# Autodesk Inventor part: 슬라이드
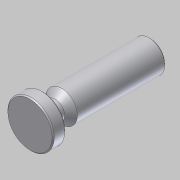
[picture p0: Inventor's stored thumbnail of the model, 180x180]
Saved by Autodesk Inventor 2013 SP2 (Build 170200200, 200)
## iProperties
Created: 2014-03
Part Number: 슬라이드
Document SubType Name: Modeling
Designer: SeoGD™[esajin.kr]
Density: 1 g/cm^3
Material: 일반
Author: SeoGD™[esajin.kr]
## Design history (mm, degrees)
sketch "스케치1"
  geometry: L1 (7.5, 114.5)-(7.5, 91.5) reference; L2 (13, 91)-(-13, 91) reference; L3 (0, 126)-(0, 69); L4 (0, 69)-(11, 69); L5 (11, 69)-(11, 75); L6 (11, 75)-(4.5, 75); L7 (4.5, 75)-(4.5, 81); L8 (4.5, 81)-(7.5, 84); L9 (7.5, 84)-(7.5, 126); L10 (7.5, 126)-(0, 126); 2 further points
  constraints: 18 end point, 4 parallel, 3 perpendicular, 1 collinear, 1 midpoint, 1 point on line, 1 vertical, 2 other
  dimensions: "d0" = 57 distance of L3.start L3.end; "d1" = 6 distance of L4.end L5.end; "d2" = 45 deg angle of L8 L7; "d3" = 9 diameter of L7 L3; "d4" = 15 distance from line of L4 L8.end; "d5" = 22 distance from line of L3.end L2; "d6" = 22 diameter of L5 L3
revolve "회전1" sketch "스케치1" stored, may be unused: angle "d7" = 90 deg
chamfer "모따기1" distance "d8" = 0.5; stored, may be unused: second distance "d9" = 2, angle "d10" = 45 deg
fillet "모깎기1" dims "d11" = 0.3
node "솔리드1"
node "참조1"
